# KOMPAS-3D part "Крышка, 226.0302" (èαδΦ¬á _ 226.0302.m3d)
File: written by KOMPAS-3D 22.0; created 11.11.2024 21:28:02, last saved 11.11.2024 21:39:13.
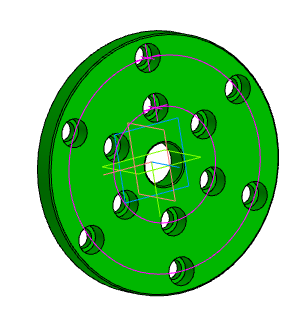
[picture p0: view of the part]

Document properties: Автор: aleksander.larionov.10@gmail.com; Полное имя файла: C:\Мои папки\Работа\Крышки, фланцы\226.0302\Крышка _ 226.0302.m3d

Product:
- Part/product: Крышка  | designation 226.0302
    Материал: Сталь 45 ГОСТ 1050-2013 (density 7810 kg/m3)
    Масса: 3.032924

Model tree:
1. Эскиз:1
2. Элемент выдавливания:1
     Расстояние 1 = 18
3. Эскиз:2  (with: Элемент выдавливания:1)
4. Отверстие:1  (with: Элемент выдавливания:1)
     Глубина выреза = 18; Диаметр отверстия = 14; Угол конуса дна = 118; Расстояние 1 = 75; Диаметр цековки = 20; Глубина цековки = 12
5. Отверстие:2  (with: Элемент выдавливания:1)
     Глубина выреза = 18; Диаметр отверстия = 14; Угол конуса дна = 118; Расстояние 1 = 40; Диаметр цековки = 20; Глубина цековки = 12
6. Массив по концентрической сетке:1  (with: Отверстие:2, Отверстие:1)  (6 pattern instances)
     Шаг 2 = 360
7. Фаска:1  (with: Элемент выдавливания:1)
     Угол = 45; Длина 1 = 1; Длина 2 = 1
8. Фаска:2  (with: Элемент выдавливания:1)  (labels: Сталь 45 ГОСТ 1050-2013)
     Угол = 45; Длина 1 = 1; Длина 2 = 1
